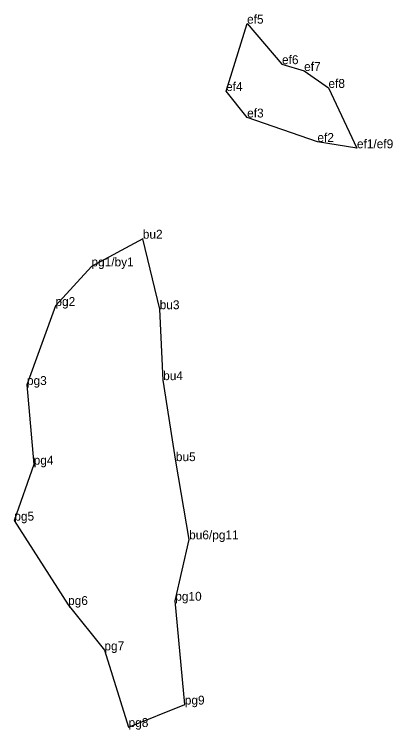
# Model space of a CAD drawing. Extents: x 2072529 to 2267990, y 436423 to 470008.
# Drawn here: x 2232279.3 to 2232534.9, y 437913.6 to 438397.2 of the extents above; entities that cross this region are included whole.
import ezdxf

# ---------------------------------------------------------------- set-up
doc = ezdxf.new("R2010")
doc.units = 0
doc.layers.add('Level 3', color=7, linetype='Continuous')
doc.layers.add('Old_Level_52', color=7, linetype='Continuous')

msp = doc.modelspace()

# ---------------------------------------------------------------- linework, layer by layer
at = {"layer": 'Level 3'}
for p, q in [((2232436.549, 438390.846), (2232436.549, 438390.846)), ((2232460.124, 438363.464), (2232460.124, 438363.464)), ((2232475.099, 438358.872), (2232475.099, 438358.872)), ((2232422.343, 438345.305), (2232422.343, 438345.305)), ((2232491.511, 438347.414), (2232491.511, 438347.414)), ((2232436.594, 438327.417), (2232436.594, 438327.417)), ((2232484.073, 438310.917), (2232484.073, 438310.917)), ((2232510.735, 438306.623), (2232510.735, 438306.623)), ((2232366.112, 438245.5), (2232366.112, 438245.5)), ((2232331.437, 438226.791), (2232331.437, 438226.791)), ((2232307.115, 438200.033), (2232307.115, 438200.033)), ((2232377.528, 438197.838), (2232377.528, 438197.838)), ((2232287.872, 438146.611), (2232287.872, 438146.611)), ((2232379.864, 438149.901), (2232379.864, 438149.901)), ((2232292.414, 438092.775), (2232292.414, 438092.775)), ((2232388.443, 438095.151), (2232388.443, 438095.151)), ((2232279.345, 438054.925), (2232279.345, 438054.925)), ((2232397.402, 438042.279), (2232397.402, 438042.279)), ((2232388.032, 438000.797), (2232388.032, 438000.797)), ((2232315.647, 437997.921), (2232315.647, 437997.921)), ((2232340.172, 437967.264), (2232340.172, 437967.264)), ((2232394.485, 437930.604), (2232394.485, 437930.604)), ((2232356.526, 437915.432), (2232356.526, 437915.432))]:
    msp.add_line(p, q, dxfattribs=at)
at = {"layer": 'Old_Level_52'}
for points in [[(2232510.735, 438306.623), (2232484.073, 438310.917), (2232436.594, 438327.417), (2232422.343, 438345.305), (2232436.549, 438390.846), (2232460.124, 438363.464), (2232475.099, 438358.872), (2232491.511, 438347.414)], [(2232331.437, 438226.791), (2232307.115, 438200.033), (2232287.872, 438146.611), (2232292.414, 438092.775), (2232279.345, 438054.925), (2232315.647, 437997.921), (2232340.172, 437967.264), (2232356.526, 437915.432), (2232394.485, 437930.604), (2232388.032, 438000.797), (2232397.402, 438042.279), (2232388.443, 438095.151), (2232379.864, 438149.901), (2232377.528, 438197.838), (2232366.112, 438245.5)]]:
    msp.add_lwpolyline(points, close=True, dxfattribs=at)

# ---------------------------------------------------------------- texts
for s, p in [('ef5', (2232436.549, 438390.846)), ('ef6', (2232460.124, 438363.464)), ('ef7', (2232475.099, 438358.872)), ('ef8', (2232491.511, 438347.414)), ('ef4', (2232422.343, 438345.305)), ('ef3', (2232436.594, 438327.417)), ('ef2', (2232484.073, 438310.917)), ('ef1/ef9', (2232510.735, 438306.623)), ('bu2', (2232366.112, 438245.5)), ('pg1/by1', (2232331.437, 438226.791)), ('pg2', (2232307.115, 438200.033)), ('bu3', (2232377.528, 438197.838)), ('bu4', (2232379.864, 438149.901)), ('pg3', (2232287.872, 438146.611)), ('pg4', (2232292.414, 438092.775)), ('bu5', (2232388.443, 438095.151)), ('pg5', (2232279.345, 438054.925)), ('bu6/pg11', (2232397.402, 438042.279)), ('pg10', (2232388.032, 438000.797)), ('pg6', (2232315.647, 437997.921)), ('pg7', (2232340.172, 437967.264)), ('pg9', (2232394.485, 437930.604)), ('pg8', (2232356.526, 437915.432))]:
    msp.add_text(s, height=6).set_placement(p)

doc.saveas('drawing.dxf')
